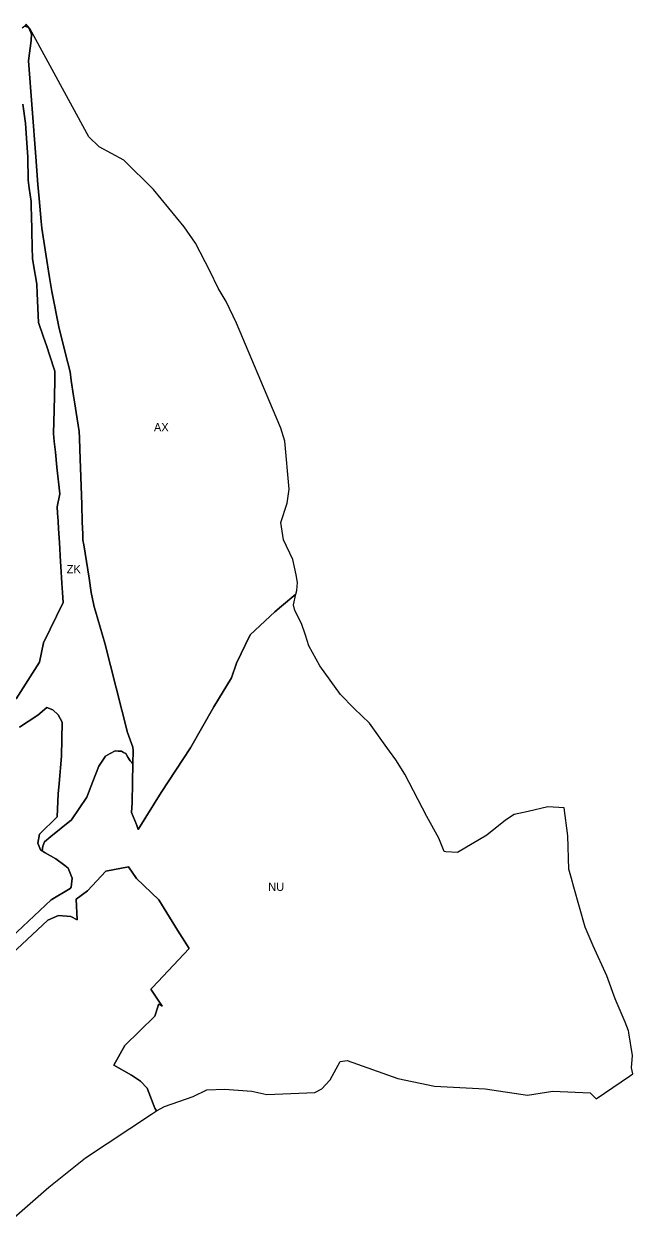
# Model space of a CAD drawing. Extents: x -521939 to -516426, y -1197857 to -1189551.
# Drawn here: x -518075 to -517337, y -1192695 to -1191238 of the extents above; entities that cross this region are included whole.
import ezdxf

# ---------------------------------------------------------------- set-up
doc = ezdxf.new("R2010")
doc.units = 0
for name, color, linetype in [('90710013', 7, 'Continuous'), ('90730013', 7, 'Continuous'), ('90750013', 7, 'Continuous'), ('90760013', 7, 'Continuous')]:
    doc.layers.add(name, color=color, linetype=linetype)

msp = doc.modelspace()

# ---------------------------------------------------------------- linework, layer by layer
at = {"layer": '90710013'}
for points in [[(-517943.1, -1192133.96), (-517942.72, -1192117.68), (-517943.23, -1192113.96), (-517949.43, -1192095.84), (-517977.06, -1191987.74), (-517988.45, -1191949.05), (-517989.99, -1191943.62), (-517990.62, -1191941.68), (-517993.58, -1191926.39), (-517996.23, -1191908.82), (-518002.55, -1191868.67), (-518003.66, -1191863.06), (-518003.92, -1191855.85), (-518004.45, -1191840.85), (-518005.14, -1191819.52), (-518007.48, -1191753.14), (-518008.01, -1191738.74), (-518008.37, -1191731.21), (-518011.89, -1191708.31), (-518013.66, -1191697.55), (-518015.16, -1191687.87), (-518018.06, -1191669.38), (-518019.12, -1191658.95), (-518024.71, -1191637.33), (-518030.63, -1191614.21), (-518032.65, -1191606.28), (-518041.53, -1191561.74), (-518044.24, -1191544.71), (-518048.48, -1191516.5), (-518053.29, -1191484.66), (-518054.39, -1191476.87), (-518056.8, -1191448.99), (-518058.21, -1191431.96), (-518060.82, -1191398.45), (-518069.47, -1191282.08), (-518066.3, -1191257.46), (-518065.96, -1191249.61), (-518068.83, -1191242.94), (-518070.5, -1191241.25), (-518073.93, -1191240.12), (-518077.16, -1191242.55)], [(-518076.64, -1191334.54), (-518073.11, -1191357.72), (-518071.88, -1191375.73), (-518070.65, -1191398.87), (-518070.14, -1191426.54), (-518068.84, -1191436.36), (-518066.6, -1191452.72), (-518066.38, -1191460.66), (-518066.15, -1191468.54), (-518065.61, -1191488.53), (-518065.06, -1191507.7), (-518064.87, -1191521.58), (-518063.98, -1191526.7), (-518059.54, -1191552.72), (-518059.04, -1191564.15), (-518057.62, -1191599.3), (-518051.82, -1191615.77), (-518047.54, -1191628.23), (-518044.03, -1191638.33), (-518037.56, -1191657.98), (-518037.63, -1191670.07), (-518038.61, -1191705.3), (-518039.39, -1191733.78), (-518038.39, -1191743.43), (-518037.01, -1191756.49), (-518035.12, -1191774.44), (-518031.59, -1191806.67), (-518034.81, -1191822.72), (-518034.38, -1191830.07), (-518033.85, -1191839.8), (-518033.34, -1191849.1), (-518032.64, -1191860.06), (-518031.81, -1191872.61), (-518031.25, -1191882.52), (-518030.38, -1191894.92), (-518029.14, -1191915.1), (-518028.46, -1191926.18), (-518027.73, -1191938.4), (-518051.56, -1191987.26), (-518056.12, -1192010.8), (-518084.56, -1192055.3)], [(-518080.71, -1192089.58), (-518058.25, -1192075.03), (-518047.38, -1192065.85), (-518040.27, -1192068.64), (-518033.52, -1192074.51), (-518028.72, -1192083.39), (-518029.53, -1192124.74), (-518032.63, -1192157.85), (-518033.84, -1192170.31), (-518034.93, -1192198.11), (-518056.16, -1192219.41), (-518058.28, -1192230.2), (-518055.2, -1192238.07), (-518053.25, -1192239.37), (-518053.25, -1192239.36), (-518052.47, -1192233.62), (-518050.31, -1192228.38), (-518042.56, -1192222), (-518030.1, -1192211.88), (-518017.63, -1192201.75), (-518008.38, -1192188), (-517999.12, -1192174.25), (-517991.83, -1192155.56), (-517984.53, -1192136.87), (-517980.44, -1192130.81), (-517976.34, -1192124.75), (-517970.55, -1192121.56), (-517964.75, -1192118.37), (-517960.88, -1192118.56), (-517957, -1192118.75), (-517954.42, -1192120.06), (-517951.84, -1192121.37), (-517949.05, -1192125.87), (-517946.25, -1192130.37), (-517944.54, -1192132.33), (-517943.1, -1192133.96)]]:
    msp.add_lwpolyline(points, dxfattribs=at)
at = {"layer": '90730013'}
msp.add_lwpolyline([(-518109.45, -1192382.02), (-518046.33, -1192323.29), (-518033.21, -1192317.57), (-518018.2, -1192319.1), (-518010.6, -1192322.82), (-518012.03, -1192297.79), (-517998.31, -1192288.04), (-517976.01, -1192263.94), (-517948.58, -1192258.68), (-517938.71, -1192273.08), (-517911.8, -1192298.65), (-517888.81, -1192335.51), (-517874.81, -1192357.96), (-517919.33, -1192405.1), (-517921.42, -1192407.14), (-517907.44, -1192427.78), (-517911.95, -1192425.26), (-517912.56, -1192427.26), (-517916.41, -1192439.93), (-517952.89, -1192475.46), (-517966.33, -1192499.14), (-517944.59, -1192511.06), (-517933.87, -1192518.63), (-517925.61, -1192526.94), (-517916.64, -1192551.13), (-517914.33, -1192554.36), (-517904.9, -1192549.16), (-517870.09, -1192537.11), (-517853.37, -1192529.23), (-517831.88, -1192528.24), (-517798.9, -1192530.79), (-517780.59, -1192534.85), (-517722.38, -1192532.36), (-517713.94, -1192527.65), (-517704.26, -1192517.36), (-517703.94, -1192516.77), (-517691.85, -1192494.5), (-517683.24, -1192493.66), (-517621.73, -1192515.48), (-517577.37, -1192524.4), (-517515.88, -1192527.65), (-517464.79, -1192535.46), (-517433.84, -1192530.84), (-517388.6, -1192532.69), (-517381.57, -1192539.95), (-517340.8, -1192512.33), (-517336.77, -1192509.6), (-517338.56, -1192502.18), (-517337.35, -1192487.59), (-517341.63, -1192460.06), (-517341.78, -1192459.09), (-517342.01, -1192457.6), (-517346.37, -1192447.19), (-517358.3, -1192418.72), (-517368.25, -1192390.88), (-517385.15, -1192354.39), (-517394.85, -1192332.07), (-517408.37, -1192283.3), (-517411.2, -1192273.11), (-517414.44, -1192261.44), (-517415.92, -1192221.1), (-517420.36, -1192187.14), (-517440.05, -1192185.9), (-517463.82, -1192191.59), (-517480.7, -1192195.55), (-517491.36, -1192202.35), (-517513.77, -1192220.34), (-517549.32, -1192241.33), (-517563.82, -1192240.76), (-517565.87, -1192240.11), (-517571.95, -1192224.17), (-517586.8, -1192197.68), (-517613.53, -1192146.34), (-517624.42, -1192129.01), (-517635, -1192114.23), (-517656.03, -1192084.87), (-517674.84, -1192067.05), (-517691.39, -1192050.02), (-517716.47, -1192015.13), (-517729.86, -1191991.06), (-517733.74, -1191977.94), (-517738.75, -1191964.07), (-517746.74, -1191948.21), (-517748.53, -1191941.31), (-517745.41, -1191928.51), (-517762.7, -1191942.88), (-517770.79, -1191949.6), (-517801.09, -1191977.67), (-517817.56, -1192011.96), (-517823.62, -1192029.85), (-517844.83, -1192064.77), (-517873.31, -1192114.59), (-517908.65, -1192168.84), (-517936.59, -1192213.7), (-517938.51, -1192207.57), (-517944.58, -1192192.89), (-517944.02, -1192181.14), (-517943.62, -1192156.22), (-517943.1, -1192133.96), (-517944.54, -1192132.33), (-517946.25, -1192130.37), (-517949.05, -1192125.87), (-517951.84, -1192121.37), (-517954.42, -1192120.06), (-517957, -1192118.75), (-517960.88, -1192118.56), (-517964.75, -1192118.37), (-517970.55, -1192121.56), (-517976.34, -1192124.75), (-517980.44, -1192130.81), (-517984.53, -1192136.87), (-517991.83, -1192155.56), (-517999.12, -1192174.25), (-518008.38, -1192188), (-518017.63, -1192201.75), (-518030.1, -1192211.88), (-518042.56, -1192222), (-518050.31, -1192228.38), (-518052.47, -1192233.62), (-518053.25, -1192239.36), (-518053.25, -1192239.37), (-518049.28, -1192242.01), (-518036.42, -1192248.98), (-518025.74, -1192257.06), (-518021.52, -1192260.23), (-518016.68, -1192272.67), (-518018.08, -1192283.32), (-518019.07, -1192284.95), (-518042.12, -1192298.66), (-518125.15, -1192376.45)], dxfattribs=at)
at = {"layer": '90750013'}
msp.add_lwpolyline([(-518100.15, -1192695.18), (-518044.98, -1192646.87), (-518000.71, -1192611.51), (-517920.39, -1192558.37), (-517914.33, -1192554.36), (-517916.64, -1192551.13), (-517925.61, -1192526.94), (-517933.87, -1192518.63), (-517944.59, -1192511.06), (-517966.33, -1192499.14), (-517952.89, -1192475.46), (-517916.41, -1192439.93), (-517912.56, -1192427.26), (-517911.95, -1192425.26), (-517907.44, -1192427.78), (-517921.42, -1192407.14), (-517919.33, -1192405.1), (-517874.81, -1192357.96), (-517888.81, -1192335.51), (-517911.8, -1192298.65), (-517938.71, -1192273.08), (-517948.58, -1192258.68), (-517976.01, -1192263.94), (-517998.31, -1192288.04), (-518012.03, -1192297.79), (-518010.6, -1192322.82), (-518018.2, -1192319.1), (-518033.21, -1192317.57), (-518046.33, -1192323.29), (-518109.45, -1192382.02)], dxfattribs=at)
at = {"layer": '90760013'}
for points in [[(-517745.41, -1191928.51), (-517744.28, -1191923.86), (-517743.34, -1191914.16), (-517745.13, -1191905.09), (-517749.22, -1191886.54), (-517760.54, -1191862.46), (-517763.62, -1191841.52), (-517756.1, -1191818.22), (-517753.63, -1191801.14), (-517758.97, -1191743.08), (-517763.64, -1191727.1), (-517769.45, -1191714.04), (-517817.26, -1191599.85), (-517829.85, -1191573.54), (-517839.82, -1191557.57), (-517849.68, -1191536.71), (-517867.02, -1191503.16), (-517880.77, -1191483.28), (-517918.12, -1191438.18), (-517954.07, -1191402.48), (-517983.92, -1191386.29), (-517996.3, -1191374.01), (-518067.84, -1191243.04), (-518071.1, -1191239.08), (-518072.39, -1191237.51), (-518073.63, -1191239.4), (-518073.93, -1191240.12), (-518070.5, -1191241.25), (-518068.83, -1191242.94), (-518065.96, -1191249.61), (-518066.3, -1191257.46), (-518069.47, -1191282.08), (-518060.82, -1191398.45), (-518058.21, -1191431.96), (-518056.8, -1191448.99), (-518054.39, -1191476.87), (-518053.29, -1191484.66), (-518048.48, -1191516.5), (-518044.24, -1191544.71), (-518041.53, -1191561.74), (-518032.65, -1191606.28), (-518030.63, -1191614.21), (-518024.71, -1191637.33), (-518019.12, -1191658.95), (-518018.06, -1191669.38), (-518015.16, -1191687.87), (-518013.66, -1191697.55), (-518011.89, -1191708.31), (-518008.37, -1191731.21), (-518008.01, -1191738.74), (-518007.48, -1191753.14), (-518005.14, -1191819.52), (-518004.45, -1191840.85), (-518003.92, -1191855.85), (-518003.66, -1191863.06), (-518002.55, -1191868.67), (-517996.23, -1191908.82), (-517993.58, -1191926.39), (-517990.62, -1191941.68), (-517989.99, -1191943.62), (-517988.45, -1191949.05), (-517977.06, -1191987.74), (-517949.43, -1192095.84), (-517943.23, -1192113.96), (-517942.72, -1192117.68), (-517943.1, -1192133.96), (-517943.62, -1192156.22), (-517944.02, -1192181.14), (-517944.58, -1192192.89), (-517938.51, -1192207.57), (-517936.59, -1192213.7), (-517908.65, -1192168.84), (-517873.31, -1192114.59), (-517844.83, -1192064.77), (-517823.62, -1192029.85), (-517817.56, -1192011.96), (-517801.09, -1191977.67), (-517770.79, -1191949.6), (-517762.7, -1191942.88), (-517745.41, -1191928.51)], [(-518084.56, -1192055.3), (-518056.12, -1192010.8), (-518051.56, -1191987.26), (-518027.73, -1191938.4), (-518028.46, -1191926.18), (-518029.14, -1191915.1), (-518030.38, -1191894.92), (-518031.25, -1191882.52), (-518031.81, -1191872.61), (-518032.64, -1191860.06), (-518033.34, -1191849.1), (-518033.85, -1191839.8), (-518034.38, -1191830.07), (-518034.81, -1191822.72), (-518031.59, -1191806.67), (-518035.12, -1191774.44), (-518037.01, -1191756.49), (-518038.39, -1191743.43), (-518039.39, -1191733.78), (-518038.61, -1191705.3), (-518037.63, -1191670.07), (-518037.56, -1191657.98), (-518044.03, -1191638.33), (-518047.54, -1191628.23), (-518051.82, -1191615.77), (-518057.62, -1191599.3), (-518059.04, -1191564.15), (-518059.54, -1191552.72), (-518063.98, -1191526.7), (-518064.87, -1191521.58), (-518065.06, -1191507.7), (-518065.61, -1191488.53), (-518066.15, -1191468.54), (-518066.38, -1191460.66), (-518066.6, -1191452.72), (-518068.84, -1191436.36), (-518070.14, -1191426.54), (-518070.65, -1191398.87), (-518071.88, -1191375.73), (-518073.11, -1191357.72), (-518076.64, -1191334.54)], [(-518125.15, -1192376.45), (-518042.12, -1192298.66), (-518019.07, -1192284.95), (-518018.08, -1192283.32), (-518016.68, -1192272.67), (-518021.52, -1192260.23), (-518025.74, -1192257.06), (-518036.42, -1192248.98), (-518049.28, -1192242.01), (-518053.25, -1192239.37), (-518055.2, -1192238.07), (-518058.28, -1192230.2), (-518056.16, -1192219.41), (-518034.93, -1192198.11), (-518033.84, -1192170.31), (-518032.63, -1192157.85), (-518029.53, -1192124.74), (-518028.72, -1192083.39), (-518033.52, -1192074.51), (-518040.27, -1192068.64), (-518047.38, -1192065.85), (-518058.25, -1192075.03), (-518080.71, -1192089.58)]]:
    msp.add_lwpolyline(points, dxfattribs=at)

# ---------------------------------------------------------------- texts
at = {"layer": '90710013'}
msp.add_text('ZK', height=10, rotation=360, dxfattribs=at).set_placement((-518023.28, -1191903))
at = {"layer": '90730013'}
msp.add_text('NU', height=10, rotation=360, dxfattribs=at).set_placement((-517779.05, -1192287.94))
at = {"layer": '90760013'}
msp.add_text('AX', height=10, rotation=0, dxfattribs=at).set_placement((-517917.56, -1191731.04))

doc.saveas('drawing.dxf')
